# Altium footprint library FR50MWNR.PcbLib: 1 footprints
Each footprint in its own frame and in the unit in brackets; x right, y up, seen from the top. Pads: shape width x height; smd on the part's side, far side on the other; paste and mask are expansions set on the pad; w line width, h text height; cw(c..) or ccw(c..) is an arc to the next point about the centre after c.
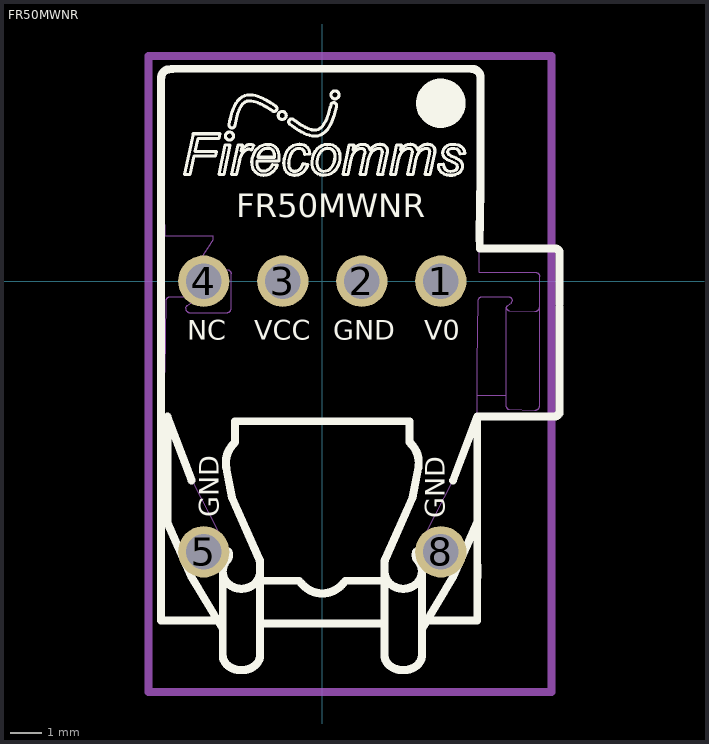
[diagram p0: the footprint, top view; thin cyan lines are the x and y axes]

## FR50MWNR [mil] "50 MBd 30° Tilted Package Non-Inverting"
height 600
pads (6):
  round 65 hole 45: 1(150,0) 2(50,0) 3(-50,0) 4(-150,0) 5(-150,-342.52) 8(150,-342.52)
Top Overlay:
  drawing of 2404 lines, arcs and shapes, not listed
  text "NC" at -171,-74 h25
  text "VCC" at -86,-74 h25
  text "GND" at 14,-74 h25
  text "V0" at 129,-74 h25
  text "GND" at 155,-300 h25
  text "GND" at -131,-299 h25
  text "FR50MWNR" at -109,81 h30
Mechanical 2:
  lines w10: -220,-520 290,-520 290,285 -220,285 -220,-520
Mechanical 19:
  drawing of 2824 lines, arcs and shapes, not listed
3D body "Tiltet.stp": height 633.84, standoff -337.66, extent -205,-721.77 273.74,268.47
